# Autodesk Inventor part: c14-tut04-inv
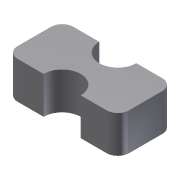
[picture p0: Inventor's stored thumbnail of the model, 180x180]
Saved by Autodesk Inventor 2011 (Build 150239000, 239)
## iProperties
Created: 2010-04
Part Number: c14-tut04-inv
Document SubType Name: Modeling
Designer: CADSoft
Density: 1 g/cm^3
Author: CADSoft
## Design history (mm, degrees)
sketch "Sketch1"
  geometry: L1 (33.666, 15.267)-(33.666, -14.733); L2 (-26.334, -14.733)-(-26.334, 15.267); L3 (-26.334, 15.267)-(-6.334, 15.267); L4 (13.666, 15.267)-(33.666, 15.267); L5 (33.666, -14.733)-(13.666, -14.733); L6 (-6.334, -14.733)-(-26.334, -14.733); A1 r 10 centre (3.666, 15.267) between (-6.334, 15.267) and (13.666, 15.267); A2 r 10 centre (3.666, -14.733) between (13.666, -14.733) and (-6.334, -14.733); 1 further point
  constraints: 12 end point, 5 parallel, 4 equal length, 4 point on circle, 2 centre point, 2 horizontal, 2 horizontal alignment, 2 perpendicular, 1 equal radius
  dimensions: "d0" = 60 distance between parallel lines of L1 L2 (= LEN); "d1" = 30 distance of L2.start L2.end (= WID); "d2" = 10 radius of A1 (= RAD)
extrude "Extrusion1" new body sketch "Sketch1" distance "d3" = 20 (= EXT); taper "d4" = 0 deg
fillet "Fillet1" dims "d5" = 6 (= FILLET)
body "Solid1"
other parameters: "LEN" = 60 [user parameter; used in 5 equation terms], "WID" = 30 (= 0.5 x LEN) [user parameter; used in 1 equation term], "RAD" = 10 (= 0.166667 x LEN) [user parameter; used in 1 equation term], "EXT" = 20 (= 0.333333 x LEN) [user parameter; used in 1 equation term], "FILLET" = 6 (= 0.1 x LEN) [user parameter; used in 1 equation term]
